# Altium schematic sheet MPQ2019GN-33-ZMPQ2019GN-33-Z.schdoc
size 127 x 101 mm
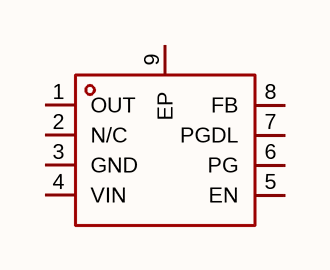
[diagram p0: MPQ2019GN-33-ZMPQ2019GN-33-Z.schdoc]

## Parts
U?  mpq2019gn-33-z  [SOIC-8_L4.9-W3.9-P1.27-LS6.0-BL-EP]  (value not drawn)

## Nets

Not connected (* = marked no-connect by the designer): U? 1(OUT) 2(N/C) 3(GND) 4(VIN) 5(EN) 6(PG) 7(PGDL) 8(FB) 9(EP)

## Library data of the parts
U? = mpq2019gn-33-z: 输出极性:正极;工作电压:40V;输出电压:3.3V;输出电流:300mA;电源纹波抑制比(PSRR):57dB@(100Hz);输出类型:固定;; Manufacturer: MPS(芯源); AddInBom: yes; ModelId: 3febf2d495b54c0da7c8bb4287865e8b; ModelTransform: 192.913,236.22,0,0,0,0,0,0,0; Output Configuration: 正极; Voltage - Supply: 40V; Output Voltage: 3.3V; Output Current: 300mA; Voltage Dropout: 480mV@(300mA); standby current: 12uA; Output Type: 固定; Number of Outputs: 1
